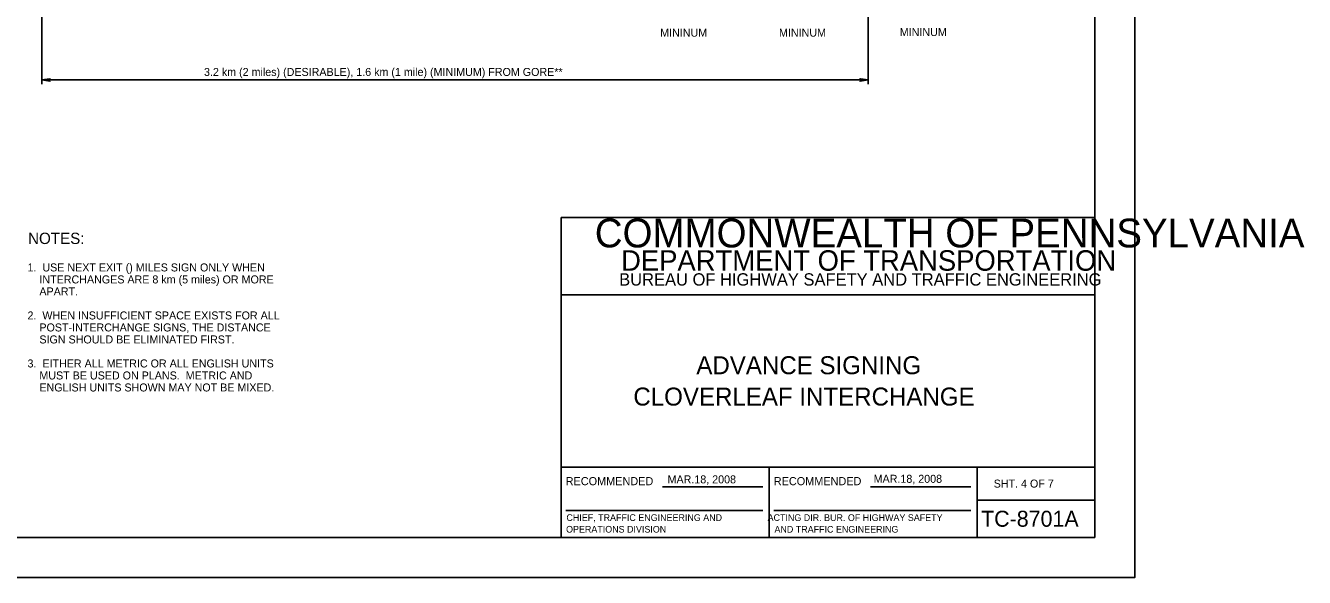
# Model space of a CAD drawing. Extents: x 640994 to 644422, y 298458 to 299646.
# Drawn here: x 643942.6 to 644421.9, y 299051.6 to 299258.5 of the extents above; entities that cross this region are included whole.
import ezdxf

# ---------------------------------------------------------------- set-up
doc = ezdxf.new("R2010")
doc.units = 0
for name, color, linetype in [('1', 7, 'Continuous'), ('2', 7, 'Continuous'), ('PLT-BNDY', 7, 'Continuous'), ('XCS-GRID-MIN', 7, 'Continuous')]:
    doc.layers.add(name, color=color, linetype=linetype)

msp = doc.modelspace()

# ---------------------------------------------------------------- linework, layer by layer
at = {"layer": '1'}
for p, q in [((644343.31, 299066.63), (644343.31, 299630.63)), ((644143.31, 299066.63), (644143.31, 299186.63)), ((644143.31, 299186.63), (644343.31, 299186.63)), ((644343.31, 299157.63), (644143.31, 299157.63)), ((644143.31, 299093), (644343.31, 299093)), ((644221.31, 299093), (644221.31, 299066.63)), ((644299.19, 299066.63), (644299.19, 299093)), ((644181.24, 299085.57), (644218.87, 299085.57)), ((644259.24, 299085.57), (644296.87, 299085.57)), ((644299.19, 299080.63), (644343.31, 299080.63)), ((644144.99, 299076.68), (644218.87, 299076.68)), ((644222.99, 299076.68), (644296.87, 299076.68)), ((644343.31, 299066.63), (643557.31, 299066.63)), ((643557.31, 299066.63), (644143.31, 299066.63))]:
    msp.add_line(p, q, dxfattribs=at)
at = {"layer": '2'}
for p, q in [((644258.31, 299314.64), (644258.31, 299236.52)), ((643948.69, 299311.52), (643948.69, 299236.52)), ((643948.69, 299238.14), (644258.31, 299238.14))]:
    msp.add_line(p, q, dxfattribs=at)
for points in [[(643951.54, 299237.78), (643951.43, 299237.99), (643948.69, 299238.14), (643951.54, 299237.78), (643951.69, 299237.66), (643948.69, 299238.14), (643951.43, 299238.28), (643951.53, 299238.48), (643948.69, 299238.14), (643951.69, 299238.62), (643951.53, 299238.48)], [(644255.46, 299238.5), (644255.56, 299238.29), (644258.31, 299238.14), (644255.46, 299238.5), (644255.31, 299238.62), (644258.31, 299238.14), (644255.57, 299238.01), (644255.47, 299237.8), (644258.31, 299238.14), (644255.31, 299237.66), (644255.47, 299237.8)]]:
    msp.add_lwpolyline(points, dxfattribs=at)
at = {"layer": 'XCS-GRID-MIN'}
msp.add_lwpolyline([(643517.31, 299645.63), (644358.31, 299645.63), (644358.31, 299051.63), (643517.31, 299051.63)], close=True, dxfattribs=at)

# ---------------------------------------------------------------- texts
at = {"layer": '1'}
for s, height, p in [('COMMONWEALTH OF PENNSYLVANIA', 10.7828, (644155.9, 299175.36)), ('DEPARTMENT OF TRANSPORTATION', 7.6837, (644165.76, 299166.61)), ('BUREAU OF HIGHWAY SAFETY AND TRAFFIC ENGINEERING', 4.6253, (644165.04, 299161.04)), ('ADVANCE SIGNING', 6.75, (644193.96, 299127.81)), ('CLOVERLEAF INTERCHANGE', 6.75, (644170.36, 299116.06)), ('RECOMMENDED', 3.048, (644144.99, 299086.2)), ('RECOMMENDED', 3.048, (644222.99, 299086.2)), ('SHT. 4 OF 7', 3, (644305.4, 299085.31)), ('TC-8701A', 6, (644300.68, 299070.63))]:
    msp.add_text(s, height=height, dxfattribs=at).set_placement(p)
at = {"layer": '2'}
for s, height, p in [(' MININUM', 3, (644179.3, 299254.36)), (' MININUM', 3, (644223.83, 299254.36)), (' MININUM', 3, (644269.09, 299254.6)), ('3.2 km (2 miles) (DESIRABLE), 1.6 km (1 mile) (MINIMUM) FROM GORE**', 3, (644009.44, 299239.64)), ('NOTES:', 4.25, (643943.5, 299176.63)), ('1.  USE NEXT EXIT () MILES SIGN ONLY WHEN', 3, (643943.29, 299166.35)), ('    INTERCHANGES ARE 8 km (5 miles) OR MORE', 3, (643943.29, 299161.85)), ('    APART.', 3, (643943.29, 299157.35)), ('2.  WHEN INSUFFICIENT SPACE EXISTS FOR ALL', 3, (643943.29, 299148.35)), ('    POST-INTERCHANGE SIGNS, THE DISTANCE', 3, (643943.29, 299143.85)), ('    SIGN SHOULD BE ELIMINATED FIRST.', 3, (643943.29, 299139.35)), ('3.  EITHER ALL METRIC OR ALL ENGLISH UNITS', 3, (643943.29, 299130.35)), ('    MUST BE USED ON PLANS.  METRIC AND', 3, (643943.29, 299125.85)), ('    ENGLISH UNITS SHOWN MAY NOT BE MIXED.', 3, (643943.29, 299121.35)), ('MAR.18, 2008', 3, (644183.18, 299086.89)), ('MAR.18, 2008', 3, (644260.41, 299087.1))]:
    msp.add_text(s, height=height, dxfattribs=at).set_placement(p)
at = {"layer": 'PLT-BNDY'}
for s, p in [('CHIEF, TRAFFIC ENGINEERING AND', (644145.28, 299072.81)), ('  ACTING DIR. BUR. OF HIGHWAY SAFETY', (644218.81, 299072.8)), ('  ACTING DIR. BUR. OF HIGHWAY SAFETY', (644218.81, 299072.8)), ('OPERATIONS DIVISION', (644145.14, 299068.44))]:
    msp.add_text(s, height=2.5, dxfattribs=at).set_placement(p)
msp.add_text('AND TRAFFIC ENGINEERING', height=2.5, rotation=360, dxfattribs=at).set_placement((644223.25, 299068.43))
msp.add_text('AND TRAFFIC ENGINEERING', height=2.5, rotation=360, dxfattribs=at).set_placement((644223.25, 299068.43))

doc.saveas('drawing.dxf')
